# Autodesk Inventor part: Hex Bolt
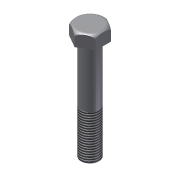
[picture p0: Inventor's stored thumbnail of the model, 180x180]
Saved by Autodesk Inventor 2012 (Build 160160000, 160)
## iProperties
Created: 2010-03
Part Number: Hex Bolt
Document SubType Name: Modeling
Designer: bhakira
Density: 1 g/cm^3
Material: Default
Author: bhakira
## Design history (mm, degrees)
sketch "Sketch1"
  geometry: C1 r 10 at (0, 0)
  constraints: 1 centre point
  dimensions: "d1" = 20 diameter of C1
extrude "Extrusion1" new body sketch "Sketch1" distance "d2" = 115; taper "d3" = 0 deg
sketch "Sketch2"
  geometry: L1 (0, 17.321)-(15, 8.66); L2 (15, 8.66)-(15, -8.66); L3 (15, -8.66)-(0, -17.321); L4 (0, -17.321)-(-15, -8.66); L5 (-15, -8.66)-(-15, 8.66); L6 (-15, 8.66)-(0, 17.321); 1 further point
  constraints: 12 end point, 13 other
  dimensions: "d4" = 30 distance between parallel lines of L2 L5
extrude "Extrusion2" join sketch "Sketch2" distance "d5" = 15; taper "d6" = 0 deg
sketch "Sketch3"
  geometry: L1 (10.19, 129.3)-(12.321, 129.3); L2 (17.321, 124.3)-(17.321, 122.815); L3 (0, -26.067)-(0, 156.403) reference; A1 r 5 centre (12.321, 124.3) between (17.321, 124.3) and (12.321, 129.3); 1 further point
  constraints: 4 end point, 2 point on circle, 2 tangent, 1 centre point
  dimensions: "d7" = 5 radius of A1
revolve "Revolution1" sketch "Sketch3" stored, may be unused: angle "d9" = 90 deg
thread "Thread1" dims "d10" = 50, "d11" = 0
body "Solid1"
other parameters: "d8" = 90 deg
